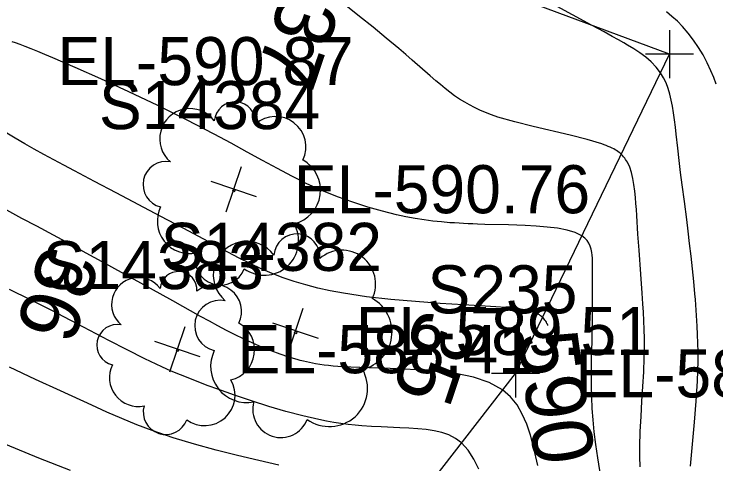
# Model space of a CAD drawing. Extents: x 1729869 to 1735532, y 648588 to 653771.
# Drawn here: x 1730251 to 1730309.4, y 652753.9 to 652791.3 of the extents above; entities that cross this region are included whole.
import ezdxf

# ---------------------------------------------------------------- set-up
doc = ezdxf.new("R2010")
doc.units = 0
for name, color, linetype in [('SURVEY - CONTOURS - Index with Text', 7, 'Continuous'), ('SURVEY - CONTOURS - Intermediate with optional Text', 7, 'Continuous'), ('SURVEY - DTM - Breaklines', 7, 'Continuous'), ('SURVEY - DTM - Breaklines - Points - Elevations', 7, 'Continuous'), ('SURVEY - DTM - Breaklines - Points - Locators', 7, 'Continuous'), ('SURVEY - DTM - Breaklines - Points - Numbers', 7, 'Continuous'), ('SURVEY - DTM - Spot Points - Elevations', 7, 'Continuous'), ('SURVEY - VEGETATION - Features - Points - Elevations', 7, 'Continuous'), ('SURVEY - VEGETATION - Features - Points - Locators', 7, 'Continuous'), ('SURVEY - VEGETATION - Features - Points - Numbers', 7, 'Continuous'), ('SURVEY - VEGETATION - Features with Text', 7, 'Continuous')]:
    doc.layers.add(name, color=color, linetype=linetype)

msp = doc.modelspace()

# ---------------------------------------------------------------- linework, layer by layer
at = {"layer": 'SURVEY - CONTOURS - Index with Text'}
msp.add_lwpolyline([(1730295.437, 652765.382), (1730295.428, 652765.405), (1730295.395, 652765.479), (1730295.36, 652765.551), (1730295.309, 652765.646), (1730295.255, 652765.737), (1730295.196, 652765.823), (1730295.133, 652765.904), (1730295.065, 652765.98), (1730294.992, 652766.052), (1730294.909, 652766.124), (1730294.821, 652766.19), (1730294.727, 652766.253), (1730294.627, 652766.311), (1730294.521, 652766.366), (1730294.408, 652766.417), (1730293.913, 652766.586), (1730293.329, 652766.715), (1730292.662, 652766.81), (1730291.914, 652766.882), (1730291.091, 652766.94), (1730288.406, 652767.092), (1730286.459, 652767.212), (1730284.419, 652767.36), (1730282.354, 652767.545), (1730280.33, 652767.774), (1730278.413, 652768.058), (1730277.31, 652768.262), (1730276.265, 652768.492), (1730275.268, 652768.75), (1730274.311, 652769.035), (1730273.385, 652769.352), (1730272.481, 652769.701), (1730271.56, 652770.097), (1730270.642, 652770.528), (1730269.717, 652770.99), (1730268.774, 652771.483), (1730267.8, 652772.004), (1730266.786, 652772.55), (1730265.04, 652773.483), (1730263.206, 652774.455), (1730259.475, 652776.419), (1730257.679, 652777.364), (1730255.996, 652778.254), (1730255.111, 652778.724), (1730254.266, 652779.177), (1730253.451, 652779.62), (1730252.653, 652780.061), (1730251.861, 652780.508), (1730251.064, 652780.969), (1730250.358, 652781.386)], dxfattribs=at)
at = {"layer": 'SURVEY - CONTOURS - Intermediate with optional Text'}
for points in [[(1730303.119, 652753.625), (1730303.101, 652754.464), (1730303.103, 652755.311), (1730303.138, 652756.553), (1730303.198, 652757.81), (1730303.274, 652759.066), (1730303.351, 652760.308), (1730303.418, 652761.521), (1730303.463, 652762.691), (1730303.475, 652763.501), (1730303.472, 652764.282), (1730303.456, 652765.038), (1730303.429, 652765.769), (1730303.394, 652766.478), (1730303.354, 652767.167), (1730303.294, 652768.078), (1730303.181, 652769.64), (1730303.034, 652771.642), (1730302.942, 652772.97), (1730302.84, 652774.52), (1730302.805, 652775.027), (1730302.767, 652775.527), (1730302.725, 652776.02), (1730302.672, 652776.569), (1730302.605, 652777.102), (1730302.518, 652777.613), (1730302.403, 652778.097), (1730302.254, 652778.549), (1730302.063, 652778.962), (1730301.992, 652779.084), (1730301.916, 652779.202), (1730301.834, 652779.316), (1730301.746, 652779.424), (1730301.652, 652779.529), (1730301.55, 652779.628), (1730301.459, 652779.708), (1730301.363, 652779.785), (1730301.262, 652779.859), (1730301.155, 652779.931), (1730301.042, 652780), (1730300.923, 652780.067), (1730300.779, 652780.143), (1730300.626, 652780.216), (1730300.465, 652780.287), (1730300.297, 652780.357), (1730300.12, 652780.425), (1730299.935, 652780.492), (1730298.715, 652780.866), (1730297.301, 652781.222), (1730294.203, 652781.933), (1730292.675, 652782.313), (1730291.266, 652782.728), (1730290.738, 652782.912), (1730290.241, 652783.103), (1730289.772, 652783.303), (1730289.329, 652783.511), (1730288.91, 652783.728), (1730288.511, 652783.954), (1730288.077, 652784.223), (1730287.663, 652784.504), (1730287.262, 652784.797), (1730286.87, 652785.103), (1730286.481, 652785.421), (1730286.09, 652785.751), (1730285.626, 652786.153), (1730284.136, 652787.462), (1730283.595, 652787.932), (1730283.025, 652788.419), (1730281.977, 652789.29), (1730280.869, 652790.192), (1730279.736, 652791.105), (1730278.613, 652792.013)], [(1730307.326, 652753.676), (1730307.487, 652755.503), (1730307.651, 652757.325), (1730307.796, 652759.092), (1730307.9, 652760.756), (1730307.932, 652761.599), (1730307.948, 652762.402), (1730307.949, 652763.171), (1730307.937, 652763.911), (1730307.914, 652764.628), (1730307.881, 652765.327), (1730307.856, 652765.774), (1730307.827, 652766.218), (1730307.796, 652766.661), (1730307.762, 652767.105), (1730307.725, 652767.553), (1730307.686, 652768.006), (1730307.589, 652769.034), (1730307.482, 652770.084), (1730307.367, 652771.141), (1730307.247, 652772.191), (1730307.123, 652773.219), (1730306.999, 652774.21), (1730306.805, 652775.69), (1730306.622, 652777.082), (1730306.493, 652778.104), (1730306.371, 652779.114), (1730306.257, 652780.124), (1730306.129, 652781.303), (1730306.061, 652781.893), (1730305.987, 652782.48), (1730305.904, 652783.062), (1730305.808, 652783.636), (1730305.711, 652784.138), (1730305.595, 652784.629), (1730305.455, 652785.105), (1730305.285, 652785.564), (1730305.078, 652786.002), (1730304.829, 652786.416), (1730304.468, 652786.88), (1730304.05, 652787.308), (1730303.588, 652787.702), (1730303.095, 652788.067), (1730302.586, 652788.404), (1730302.074, 652788.717), (1730301.764, 652788.898), (1730301.306, 652789.159), (1730300.805, 652789.437), (1730300.112, 652789.816), (1730299.072, 652790.376), (1730295.908, 652792.08)], [(1730309.461, 652785.46), (1730309.255, 652786.022), (1730309.024, 652786.584), (1730308.715, 652787.242), (1730308.368, 652787.891), (1730307.987, 652788.523), (1730307.573, 652789.132), (1730307.13, 652789.71), (1730306.659, 652790.251), (1730306.224, 652790.694), (1730305.774, 652791.106), (1730305.315, 652791.488)], [(1730299.884, 652752.602), (1730299.585, 652754.356), (1730299.425, 652755.461), (1730299.298, 652756.513), (1730299.201, 652757.518), (1730299.131, 652758.482), (1730299.085, 652759.413), (1730299.062, 652760.317), (1730299.057, 652761.096), (1730299.064, 652761.861), (1730299.079, 652762.613), (1730299.116, 652764.084), (1730299.133, 652764.806), (1730299.143, 652765.582), (1730299.148, 652766.344), (1730299.149, 652768.487), (1730299.155, 652769.408), (1730299.163, 652770.206), (1730299.162, 652770.473), (1730299.156, 652770.731), (1730299.144, 652770.981), (1730299.122, 652771.222), (1730299.091, 652771.454), (1730299.035, 652771.728), (1730298.954, 652771.987), (1730298.843, 652772.229), (1730298.696, 652772.454), (1730298.507, 652772.658), (1730298.271, 652772.84), (1730297.722, 652773.11), (1730297.035, 652773.315), (1730296.24, 652773.464), (1730295.37, 652773.57), (1730294.457, 652773.642), (1730293.532, 652773.691), (1730292.838, 652773.719), (1730292.157, 652773.741), (1730290.193, 652773.795), (1730289.567, 652773.814), (1730289.179, 652773.828), (1730288.796, 652773.843), (1730288.416, 652773.862), (1730288.037, 652773.883), (1730287.658, 652773.907), (1730287.277, 652773.934), (1730286.578, 652773.995), (1730285.865, 652774.072), (1730285.136, 652774.168), (1730284.387, 652774.285), (1730283.615, 652774.426), (1730282.818, 652774.595), (1730281.654, 652774.88), (1730280.443, 652775.224), (1730279.194, 652775.628), (1730277.916, 652776.092), (1730276.618, 652776.618), (1730275.31, 652777.206), (1730274.116, 652777.795), (1730272.906, 652778.429), (1730271.668, 652779.103), (1730270.386, 652779.812), (1730269.047, 652780.549), (1730267.637, 652781.308), (1730265.341, 652782.494), (1730262.941, 652783.679), (1730260.531, 652784.827), (1730258.206, 652785.899), (1730256.061, 652786.858), (1730254.189, 652787.666), (1730253.532, 652787.941), (1730252.933, 652788.186), (1730252.39, 652788.403), (1730251.901, 652788.592), (1730251.466, 652788.755), (1730251.082, 652788.893), (1730250.796, 652788.99)], [(1730294.611, 652753.711), (1730294.247, 652755.266), (1730293.977, 652756.246), (1730293.671, 652757.162), (1730293.307, 652758.005), (1730292.865, 652758.767), (1730292.326, 652759.439), (1730291.669, 652760.011), (1730290.552, 652760.63), (1730289.235, 652761.075), (1730287.781, 652761.378), (1730286.254, 652761.571), (1730284.715, 652761.685), (1730283.228, 652761.752), (1730282.289, 652761.785), (1730280.561, 652761.841), (1730279.77, 652761.87), (1730279.027, 652761.903), (1730278.33, 652761.943), (1730277.928, 652761.972), (1730277.541, 652762.005), (1730277.166, 652762.043), (1730276.8, 652762.087), (1730276.441, 652762.137), (1730276.087, 652762.194), (1730275.833, 652762.24), (1730275.58, 652762.291), (1730275.326, 652762.345), (1730275.07, 652762.404), (1730274.812, 652762.469), (1730274.551, 652762.538), (1730273.848, 652762.745), (1730273.123, 652762.987), (1730272.379, 652763.261), (1730271.62, 652763.565), (1730270.852, 652763.898), (1730270.079, 652764.257), (1730269.373, 652764.603), (1730268.665, 652764.967), (1730267.953, 652765.345), (1730267.235, 652765.736), (1730266.509, 652766.136), (1730264.19, 652767.421), (1730258.297, 652770.677), (1730256.983, 652771.399), (1730255.634, 652772.136), (1730254.256, 652772.882), (1730252.854, 652773.632), (1730251.615, 652774.289), (1730250.35, 652774.965)], [(1730255.676, 652753.313), (1730253.024, 652754.337), (1730250.282, 652755.475), (1730247.504, 652756.715), (1730244.74, 652758.043), (1730242.043, 652759.447), (1730239.465, 652760.914), (1730237.436, 652762.174), (1730235.532, 652763.436), (1730233.759, 652764.67), (1730232.122, 652765.843), (1730230.628, 652766.925), (1730229.282, 652767.883), (1730228.831, 652768.194), (1730228.397, 652768.489), (1730227.977, 652768.77), (1730227.164, 652769.304), (1730226.764, 652769.564)], [(1730289.686, 652753.416), (1730289.28, 652754.255), (1730288.805, 652754.997), (1730288.25, 652755.608), (1730287.745, 652755.982), (1730287.189, 652756.266), (1730286.59, 652756.473), (1730285.957, 652756.618), (1730285.295, 652756.716), (1730284.613, 652756.783), (1730283.862, 652756.834), (1730283.098, 652756.871), (1730281.538, 652756.934), (1730280.746, 652756.973), (1730279.948, 652757.027), (1730279.369, 652757.079), (1730278.786, 652757.142), (1730278.195, 652757.219), (1730277.594, 652757.311), (1730276.981, 652757.418), (1730276.353, 652757.543), (1730275.012, 652757.852), (1730273.618, 652758.225), (1730272.192, 652758.648), (1730270.755, 652759.107), (1730269.329, 652759.589), (1730267.934, 652760.082), (1730267.145, 652760.368), (1730266.368, 652760.658), (1730265.598, 652760.955), (1730264.83, 652761.264), (1730264.059, 652761.588), (1730263.278, 652761.933), (1730261.851, 652762.605), (1730260.379, 652763.34), (1730258.862, 652764.126), (1730255.694, 652765.789), (1730254.043, 652766.64), (1730252.332, 652767.5), (1730250.575, 652768.375)], [(1730273.025, 652753.754), (1730271.343, 652754.142), (1730269.593, 652754.559), (1730267.804, 652755.011), (1730266.003, 652755.503), (1730264.22, 652756.04), (1730262.481, 652756.627), (1730261.201, 652757.11), (1730259.946, 652757.623), (1730258.699, 652758.165), (1730257.443, 652758.732), (1730254.832, 652759.938), (1730252.756, 652760.89), (1730250.573, 652761.898)]]:
    msp.add_lwpolyline(points, dxfattribs=at)
at = {"layer": 'SURVEY - DTM - Breaklines'}
msp.add_lwpolyline([(1730262.708, 652722.711), (1730292.739, 652761.389), (1730305.577, 652787.964), (1730274.792, 652799.379), (1730218.463, 652820.587)], dxfattribs=at)
at = {"layer": 'SURVEY - DTM - Breaklines - Points - Locators'}
for p, q in [((1730305.577, 652789.964), (1730305.577, 652785.964)), ((1730307.577, 652787.964), (1730303.577, 652787.964)), ((1730292.739, 652763.389), (1730292.739, 652759.389)), ((1730294.739, 652761.389), (1730290.739, 652761.389))]:
    msp.add_line(p, q, dxfattribs=at)
at = {"layer": 'SURVEY - VEGETATION - Features - Points - Locators'}
for p, q in [((1730268.633, 652774.824), (1730269.913, 652778.614)), ((1730271.168, 652776.079), (1730267.378, 652777.359)), ((1730273.779, 652763.026), (1730275.059, 652766.816)), ((1730276.314, 652764.281), (1730272.524, 652765.561)), ((1730263.938, 652761.509), (1730265.218, 652765.299)), ((1730266.473, 652762.764), (1730262.683, 652764.044))]:
    msp.add_line(p, q, dxfattribs=at)
at = {"layer": 'SURVEY - VEGETATION - Features with Text'}
for centre, radius in [((1730269.279, 652776.592), 0.088), ((1730274.426, 652764.78), 0.0978), ((1730264.583, 652763.291), 0.0783)]:
    msp.add_circle(centre, radius, dxfattribs=at)
for centre, radius, start, end in [((1730269.367, 652782.257), 1.732, 356.36539, 175.11103), ((1730265.615, 652780.911), 2.518, 36.38607, 229.80576), ((1730272.752, 652780.244), 2.523, 334.24923, 131.03815), ((1730263.624, 652777.107), 1.916, 79.00474, 256.32389), ((1730273.625, 652776.643), 2.875, 283.30197, 60.8262), ((1730265.617, 652774.067), 2.715, 154.29179, 281.13746), ((1730271.814, 652772.416), 2.856, 234.1978, 30.03629), ((1730274.524, 652771.074), 1.924, 356.36539, 175.11103), ((1730270.354, 652769.579), 2.798, 36.38607, 229.80576), ((1730278.285, 652768.838), 2.804, 334.24923, 131.03815), ((1730268.171, 652770.839), 2.106, 164.4507, 339.45098), ((1730264.662, 652768.327), 1.54, 356.36539, 175.11103), ((1730261.326, 652767.13), 2.238, 36.38607, 229.80576), ((1730267.671, 652766.537), 2.243, 334.24923, 131.03815), ((1730268.143, 652765.352), 2.129, 79.00474, 256.32389), ((1730279.255, 652764.837), 3.194, 283.30197, 60.8262), ((1730268.447, 652763.337), 2.556, 283.30197, 60.8262), ((1730259.557, 652763.749), 1.703, 79.00474, 256.32389), ((1730270.357, 652761.974), 3.016, 154.29179, 281.13746), ((1730261.328, 652761.047), 2.413, 154.29179, 281.13746), ((1730277.243, 652760.14), 3.174, 234.1978, 30.03629), ((1730266.837, 652759.579), 2.539, 234.1978, 30.03629), ((1730263.598, 652758.177), 1.872, 164.4507, 339.45098), ((1730273.195, 652758.387), 2.34, 164.4507, 339.45098)]:
    msp.add_arc(centre, radius, start, end, dxfattribs=at)

# ---------------------------------------------------------------- texts
at = {"layer": 'SURVEY - CONTOURS - Index with Text'}
msp.add_text('590', height=5, rotation=278.00379, dxfattribs=at).set_placement((1730292.875, 652764.602))
at = {"layer": 'SURVEY - DTM - Breaklines - Points - Elevations'}
msp.add_text('EL-589.31', height=4, dxfattribs=at).set_placement((1730297.739, 652759.389))
at = {"layer": 'SURVEY - DTM - Breaklines - Points - Numbers'}
msp.add_text('S235', height=4, dxfattribs=at).set_placement((1730285.403, 652766.389))
at = {"layer": 'SURVEY - DTM - Spot Points - Elevations'}
msp.add_text('EL-590.87', height=4, dxfattribs=at).set_placement((1730254.578, 652785.378))
at = {"layer": 'SURVEY - VEGETATION - Features - Points - Elevations'}
for s, p in [('EL-590.76', (1730274.273, 652774.719)), ('EL-589.51', (1730279.419, 652762.921)), ('EL-588.41', (1730269.578, 652761.404))]:
    msp.add_text(s, height=4, dxfattribs=at).set_placement(p)
at = {"layer": 'SURVEY - VEGETATION - Features - Points - Numbers'}
for s, p in [('S14384', (1730258.033, 652781.719)), ('S14382', (1730263.179, 652769.921)), ('S14383', (1730253.338, 652768.404))]:
    msp.add_text(s, height=4, dxfattribs=at).set_placement(p)
at = {"layer": 'SURVEY - VEGETATION - Features with Text'}
for s, p in [('37', (1730273.417, 652793.319)), ('36', (1730253.449, 652772.281)), ('35', (1730284.808, 652766.954))]:
    msp.add_text(s, height=5, rotation=251.33372, dxfattribs=at).set_placement(p)

doc.saveas('drawing.dxf')
